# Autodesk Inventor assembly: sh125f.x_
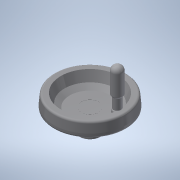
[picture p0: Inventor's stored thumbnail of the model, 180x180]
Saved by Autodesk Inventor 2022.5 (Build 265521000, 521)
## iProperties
Part Number: sh125f.x_
Material: 一般
Document SubType Name: Assembly
Designer: ImaoCorp
Sending System: SOLIDWORKS 2017-2017317
MC: AMD64
MC_MODEL: Intel64 Family 6 Model 60 Stepping 3, GenuineIntel
OS: Windows_NT
FRU: Parasolid Version 29.0, build 201,  4-17-2017
FORMAT: text
GUISE: transmit
KEY: sh125f
FILE: sh125f.x_t
DATE: Wed Sep 18 16:14:18 2019
Author: ImaoCorp
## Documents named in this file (3)
- X:\14_SW2022-Inv2022\00_全2023-1023新製品(TCC)まで\s\sh125f\SH125F.iam
- X:\14_SW2022-Inv2022\00_全2023-1023新製品(TCC)まで\s\sh125f\sh125f_01.ipt
- X:\14_SW2022-Inv2022\00_全2023-1023新製品(TCC)まで\s\sh125f\sh125f_02.ipt
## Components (2 placed, 2 different names)
1. sh125f_01
2. sh125f_02
